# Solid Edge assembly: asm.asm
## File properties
Author: Deepak Maini
Template: Normal.asm
Last saved by: MYPC
Revision: 4
Application: Solid Edge
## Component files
endplatemod.par
diskmod.par
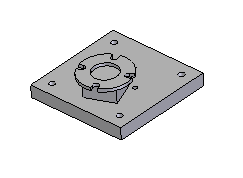
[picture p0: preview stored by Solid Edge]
